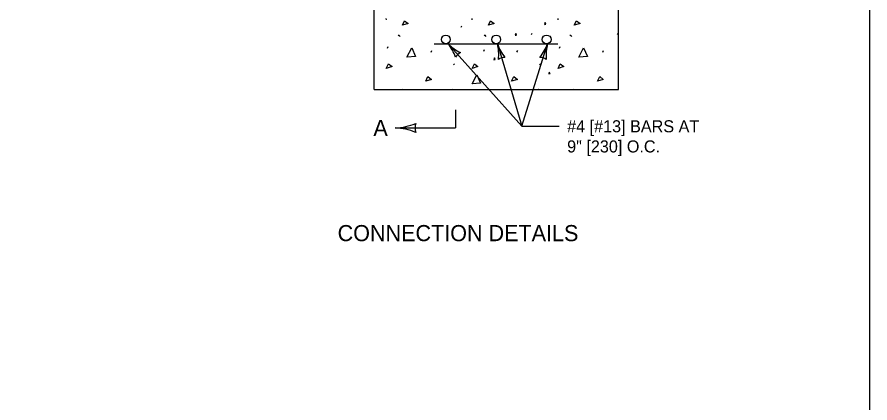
# Model space of a CAD drawing. Extents: x 49991.4 to 50021, y 49987.6 to 50011.4.
# Drawn here: x 50004.383 to 50008.615, y 50006.11 to 50008.025 of the extents above; entities that cross this region are included whole.
import ezdxf

# ---------------------------------------------------------------- set-up
doc = ezdxf.new("R2010")
doc.units = 0
for name, color, linetype in [('Level 1', 7, 'Continuous'), ('Level 2', 7, 'Continuous'), ('Level 3', 7, 'Continuous'), ('Level 6', 7, 'Continuous')]:
    doc.layers.add(name, color=color, linetype=linetype)

msp = doc.modelspace()

# ---------------------------------------------------------------- linework, layer by layer
at = {"layer": 'Level 1'}
for p, q in [((50007.3661, 50007.6648), (50007.3661, 50008.2517)), ((50006.1541, 50007.6648), (50006.1541, 50008.1648)), ((50006.2127, 50008.0185), (50006.2136, 50008.0105)), ((50006.6391, 50008.0185), (50006.6399, 50008.0105)), ((50007.0654, 50008.0185), (50007.0663, 50008.0105)), ((50006.5862, 50007.9741), (50006.5898, 50007.9821)), ((50006.9351, 50007.9378), (50006.9387, 50007.9458)), ((50007.3615, 50007.9378), (50007.365, 50007.9458)), ((50006.2733, 50007.9368), (50006.2769, 50007.9315)), ((50006.2779, 50007.9348), (50006.2814, 50007.9294)), ((50006.6997, 50007.9368), (50006.7032, 50007.9315)), ((50006.7042, 50007.9348), (50006.7078, 50007.9294)), ((50007.126, 50007.9368), (50007.1296, 50007.9315)), ((50007.1306, 50007.9348), (50007.1342, 50007.9294)), ((50006.2209, 50007.871), (50006.2245, 50007.879)), ((50006.4368, 50007.8505), (50006.4404, 50007.8585)), ((50006.453, 50007.8918), (50007.0661, 50007.8918)), ((50006.6983, 50007.8565), (50006.7018, 50007.8645)), ((50006.8632, 50007.8505), (50006.8667, 50007.8585)), ((50007.0736, 50007.871), (50007.0772, 50007.879)), ((50007.2896, 50007.8505), (50007.2931, 50007.8585)), ((50006.5478, 50007.7937), (50006.5514, 50007.7884)), ((50006.9742, 50007.7937), (50006.9777, 50007.7884)), ((50006.1541, 50007.6648), (50007.3661, 50007.6648)), ((50006.2945, 50007.6648), (50006.2965, 50007.6694)), ((50006.7208, 50007.6648), (50006.7229, 50007.6694)), ((50007.1472, 50007.6648), (50007.1493, 50007.6694))]:
    msp.add_line(p, q, dxfattribs=at)
for points in [[(50008.6146, 50011.2628), (50000.3356, 50011.2628), (50000.3356, 50000.0624), (50008.6146, 50000.0624)], [(50007.003, 50007.9976), (50007.0001, 50007.9889), (50007.0066, 50007.9904)], [(50006.8579, 50007.9431), (50006.855, 50007.9344), (50006.8615, 50007.9359)], [(50006.7516, 50007.8222), (50006.7487, 50007.8135), (50006.7552, 50007.815)], [(50007.0235, 50007.7521), (50007.0206, 50007.7434), (50007.0271, 50007.7449)]]:
    msp.add_lwpolyline(points, close=True, dxfattribs=at)
for points in [[(50006.2947, 50007.984), (50006.3054, 50008.0062), (50006.3231, 50007.9929), (50006.2947, 50007.984)], [(50006.7211, 50007.984), (50006.7318, 50008.0062), (50006.7495, 50007.9929), (50006.7211, 50007.984)], [(50007.1475, 50007.984), (50007.1581, 50008.0062), (50007.1759, 50007.9929), (50007.1475, 50007.984)], [(50006.3169, 50007.8266), (50006.3409, 50007.8719), (50006.3596, 50007.8301), (50006.3178, 50007.8266)], [(50007.1697, 50007.8266), (50007.1937, 50007.8719), (50007.2123, 50007.8301), (50007.1706, 50007.8266)], [(50006.2147, 50007.7706), (50006.2253, 50007.7928), (50006.2431, 50007.7795), (50006.2147, 50007.7706)], [(50006.6411, 50007.7706), (50006.6517, 50007.7928), (50006.6695, 50007.7795), (50006.6411, 50007.7706)], [(50007.0674, 50007.7706), (50007.0781, 50007.7928), (50007.0958, 50007.7795), (50007.0674, 50007.7706)], [(50006.6403, 50007.6932), (50006.6643, 50007.7385), (50006.6829, 50007.6967), (50006.6412, 50007.6932)], [(50006.4103, 50007.7071), (50006.421, 50007.7294), (50006.4388, 50007.716), (50006.4103, 50007.7071)], [(50006.8367, 50007.7071), (50006.8474, 50007.7294), (50006.8651, 50007.716), (50006.8367, 50007.7071)], [(50007.2631, 50007.7071), (50007.2738, 50007.7294), (50007.2915, 50007.716), (50007.2631, 50007.7071)], [(50006.5428, 50007.6648), (50006.543, 50007.6666), (50006.5447, 50007.6648)], [(50006.9691, 50007.6648), (50006.9694, 50007.6666), (50006.9711, 50007.6648)]]:
    msp.add_lwpolyline(points, dxfattribs=at)
for centre in [(50006.5101, 50007.9139), (50006.7601, 50007.9139), (50007.0101, 50007.9139)]:
    msp.add_circle(centre, 0.0221, dxfattribs=at)
at = {"layer": 'Level 3'}
for p, q in [((50006.5202, 50007.8942), (50006.8865, 50007.4831)), ((50006.7657, 50007.8925), (50006.8865, 50007.4831)), ((50006.8865, 50007.4831), (50007.0153, 50007.8924)), ((50006.8865, 50007.4831), (50007.0721, 50007.4831))]:
    msp.add_line(p, q, dxfattribs=at)
for centre, radius, start, end in [((50006.3482, 50007.7533), 0.2223, 19.157, 39.3405), ((50006.6863, 50008.0576), 0.233, 224.5283, 243.7781), ((50006.5501, 50007.8385), 0.2223, 353.8903, 14.0738), ((50006.9857, 50007.9694), 0.233, 199.2616, 218.5114), ((50006.8061, 50007.9678), 0.2223, 319.9928, 340.1763), ((50007.2407, 50007.8335), 0.233, 165.3641, 184.614), ((50006.6055, 50007.7985), 0.0548, 113.8398, 149.5621), ((50006.802, 50007.7696), 0.0548, 88.5731, 124.2954), ((50006.9768, 50007.7701), 0.0548, 54.6756, 90.398), ((50006.2441, 50007.7853), 0.3107, 272.8273, 292.0772), ((50006.4304, 50007.475), 0.073, 162.1388, 197.8612), ((50006.2472, 50007.1788), 0.2964, 67.456, 87.6395)]:
    msp.add_arc(centre, radius, start, end, dxfattribs=at)
at = {"layer": 'Level 6'}
for p in [(50006.5589, 50007.5648), (50006.2594, 50007.475)]:
    msp.add_line(p, (50006.5589, 50007.475), dxfattribs=at)

# ---------------------------------------------------------------- texts
at = {"layer": 'Level 2'}
for s, height, p in [('A', 0.08, (50006.1507, 50007.435)), ('#4 [#13] BARS AT', 0.06, (50007.1121, 50007.4531)), ('9" [230] O.C.', 0.06, (50007.1121, 50007.3531)), ('CONNECTION DETAILS', 0.08, (50005.9732, 50006.913))]:
    msp.add_text(s, height=height, dxfattribs=at).set_placement(p)

doc.saveas('drawing.dxf')
